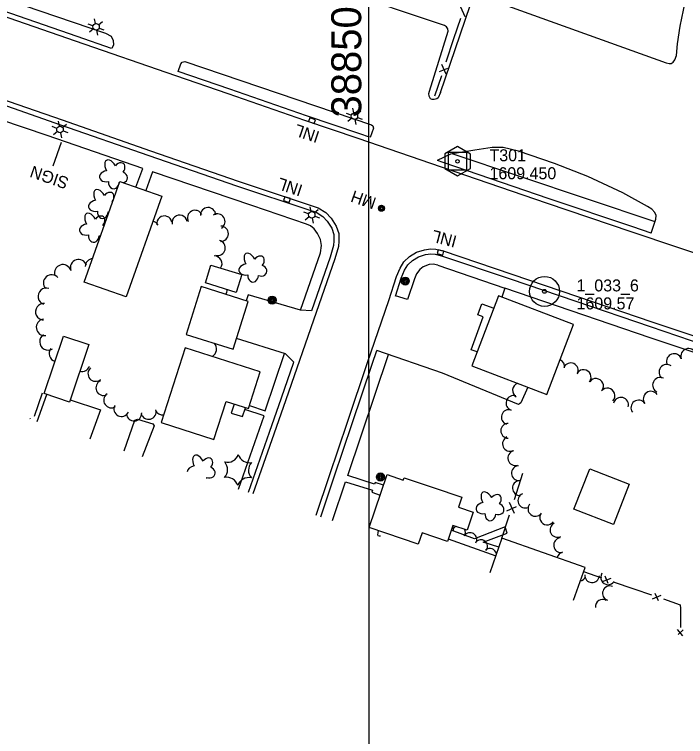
# Model space of a CAD drawing. Extents: x 189384 to 193282, y 256970 to 260388.
# Drawn here: x 191469.2 to 191805.5, y 258599.8 to 258961.6 of the extents above; entities that cross this region are included whole.
import ezdxf

# ---------------------------------------------------------------- set-up
doc = ezdxf.new("R2010")
doc.units = 0
for name, color, linetype in [('E_DRN_Grate', 7, 'Continuous'), ('E_DWY', 7, 'Continuous'), ('E_LAND_Vegetation', 7, 'Continuous'), ('E_MAP_Control', 7, 'Continuous'), ('E_MAP_GridLines', 7, 'Continuous'), ('E_MAP_PassPoints', 7, 'Continuous'), ('E_MISCPROP', 7, 'Continuous'), ('E_MISCPROP_HvyDash', 7, 'Continuous'), ('E_MISCPROP_HvyLine', 7, 'Continuous'), ('E_MISCPROP_Railing', 7, 'Continuous'), ('E_PATH_Sidewalk', 7, 'Continuous'), ('E_RDWY', 7, 'Continuous')]:
    doc.layers.add(name, color=color, linetype=linetype)

# ---------------------------------------------------------------- blocks, each defined once
blk = doc.blocks.new('TP_1')
at = {"layer": 'E_MAP_Control'}
for points in [[(-6.41, 3.76), (-6.41, -3.63), (0.05, -7.35), (6.44, -3.69), (6.44, 3.64), (-0.08, 7.36)], [(-4.5, -4.5), (-4.5, 4.5), (4.5, 4.5), (4.5, -4.5)]]:
    blk.add_lwpolyline(points, close=True, dxfattribs=at)
blk.add_circle((0, 0), 0.871, dxfattribs=at)
blk = doc.blocks.new('PP_1')
at = {"layer": 'E_MAP_PassPoints'}
for radius in [7.5, 0.96]:
    blk.add_circle((0, 0), radius, dxfattribs=at)
blk = doc.blocks.new('LTP')
at = {"layer": 'E_MISCPROP'}
for p, q in [((-0.78, 1.46), (-1.98, 3.76)), ((-1.61, 0.09), (-4.22, 0.17)), ((0.86, 1.37), (2.22, 3.6)), ((1.66, 0), (4.18, -0.06)), ((-0.86, -1.4), (-2.22, -3.59)), ((0.78, -1.44), (2.02, -3.62))]:
    blk.add_line(p, q, dxfattribs=at)
blk.add_circle((0.02, 0.01), 1.64, dxfattribs=at)
blk = doc.blocks.new('POLE')
at = {"layer": 'E_MISCPROP'}
for radius in [2.02, 1.51, 1.01, 0.504]:
    blk.add_circle((0.03, -0.09), radius, dxfattribs=at)
blk = doc.blocks.new('SIGN')
at = {"layer": 'E_MISCPROP'}
blk.add_text('SIGN', height=6, rotation=0, dxfattribs=at).set_placement((0, -3))
blk = doc.blocks.new('MHO')
at = {"layer": 'E_DRN_Grate'}
for centre, radius in [((0.04, -0.06), 1.5), ((0.04, -0.06), 1.22), ((0.04, -0.07), 0.968), ((0.01, -0.08), 0.605)]:
    blk.add_circle(centre, radius, dxfattribs=at)
blk = doc.blocks.new('INLT')
at = {"layer": 'E_MISCPROP_Railing'}
blk.add_lwpolyline([(3, -2), (3, 0), (0, 0), (0, -2), (3, -2)], dxfattribs=at)
blk = doc.blocks.new('INL')
at = {"layer": 'E_MISCPROP_Railing'}
blk.add_text('INL', height=6, rotation=0, dxfattribs=at).set_placement((-5.79, -2.75))
blk = doc.blocks.new('INL_1')
at = {"layer": 'E_MISCPROP_Railing'}
blk.add_text('INL', height=6, rotation=359.9999, dxfattribs=at).set_placement((-5.79, -2.75))
blk = doc.blocks.new('INL_2')
at = {"layer": 'E_MISCPROP_Railing'}
blk.add_text('INL', height=6, rotation=359.9999, dxfattribs=at).set_placement((-5.79, -2.75))
blk = doc.blocks.new('PINEL')
at = {"layer": 'E_LAND_Vegetation'}
for centre, start, end in [((-8.23, 7.26), 275.2112, 0.9761), ((2.17, 10.66), 215.2112, 300.9761), ((10.31, 3.35), 155.2112, 240.9761), ((-10.49, -3.45), 335.2112, 60.9761), ((8.05, -7.36), 95.2112, 180.9761), ((-2.35, -10.75), 35.2112, 120.9761)]:
    blk.add_arc(centre, 5.72, start, end, dxfattribs=at)
blk = doc.blocks.new('TREE')
at = {"layer": 'E_LAND_Vegetation'}
for centre, major_axis, ratio in [((-1.07, 3.38), (0.91, -3.32), 0.782863), ((2.88, 1.66), (-3.52, -1.95), 0.691916), ((-3.74, -0.07), (3.29, -0.08), 0.832022), ((-1.48, -3.66), (1.2, 3.24), 0.716896), ((2.54, -2.64), (-3.34, 3.06), 0.560249)]:
    blk.add_ellipse(centre, major_axis=major_axis, ratio=ratio, start_param=1.570796, end_param=4.712389, dxfattribs=at)

msp = doc.modelspace()

# ---------------------------------------------------------------- linework, layer by layer
at = {"layer": 'E_DWY'}
for points in [[(191682.66, 258922.4), (191681.57, 258919.82), (191680.85, 258919.25), (191679.6, 258918.89), (191678.51, 258918.91), (191677.77, 258919.33), (191677.07, 258920.57), (191676.84, 258921.92), (191677.19, 258923.18), (191686.53, 258953.16), (191686.41, 258954.33), (191685.67, 258955.42), (191684.69, 258956.02), (191631.75, 258973.9), (191560.77, 258998.17), (191543.64, 259004.34), (191515.7, 259014.96)], [(191682.66, 258922.4), (191697.63, 258965.98), (191698.76, 258968.4), (191700.51, 258969.51), (191702.94, 258969.96), (191705.59, 258969.84), (191795.73, 258937.33), (191797.22, 258936.96), (191798.22, 258936.97), (191799.23, 258937.68), (191800.15, 258938.79), (191800.88, 258941.07), (191801.39, 258946.78), (191802.75, 258955.61), (191805.35, 258967.79), (191808.61, 258979.78)], [(191474.06, 258966.02), (191514.83, 258952.16), (191517.69, 258950.67), (191518.63, 258948.55), (191518.85, 258946.38), (191518.04, 258944.49)], [(191551.28, 258933.04), (191552.58, 258936.88), (191553.29, 258937.63), (191554.67, 258937.93), (191648.09, 258906.28), (191648.83, 258905.68), (191649.06, 258904.62), (191647.42, 258899.98)], [(191687.77, 258891.61), (191681.09, 258888.39)], [(191788.32, 258851.94), (191790.65, 258858.94), (191790.82, 258860.82), (191790.02, 258862.35), (191788.56, 258863.96), (191786.42, 258865.34), (191774.08, 258872.21), (191756.54, 258880.45), (191739.78, 258886.8), (191721.84, 258893.13), (191714.16, 258894.97), (191708.54, 258894.84), (191699.89, 258893.63), (191692.76, 258892.35), (191687.77, 258891.61)], [(191681.36, 258835.87), (191679.06, 258836.42), (191677.09, 258836.36), (191673.97, 258835.14), (191672.38, 258833.79), (191670.7, 258831.64), (191669.7, 258829.17), (191666.16, 258818.74), (191660.22, 258820.5)], [(191681.36, 258835.87), (191714.95, 258824.39), (191713.37, 258819.95)], [(191618.11, 258813.14), (191612.52, 258813.41), (191586.27, 258821.14), (191585.3, 258818.16)], [(191701.07, 258792.45), (191698, 258793.58), (191704.14, 258810.01), (191701.45, 258811), (191703.49, 258816.53), (191709.42, 258814.44)], [(191609.14, 258787.36), (191605.05, 258791.47), (191580.55, 258799.15)], [(191683.73, 258781.76), (191650.86, 258793.22)], [(191726.43, 258774.82), (191722.96, 258767.03), (191722.28, 258766.48), (191721.71, 258766.22), (191683.73, 258781.76)], [(191480.62, 258757.62), (191485.46, 258771.16)], [(191497.22, 258768.48), (191512.43, 258763.54), (191506.94, 258748.78)], [(191524.22, 258742.97), (191529.58, 258758.3), (191530.86, 258758.75), (191538.6, 258756.42), (191539.17, 258755.43), (191533.25, 258739.94)]]:
    msp.add_lwpolyline(points, dxfattribs=at)
at = {"layer": 'E_LAND_Vegetation'}
for centre, radius, start, end in [((191559.74, 258859.61), 3.83, 27.8715, 207.8715), ((191566.28, 258860.99), 3.83, 2.1227, 182.1227), ((191544.38, 258856.8), 3.83, 10.2735, 190.2735), ((191552.01, 258857.16), 3.83, 10.6742, 190.6742), ((191570.94, 258857.82), 3.83, 301.7429, 121.7429), ((191537.96, 258854.11), 3.83, 29.4733, 80.6477), ((191572.58, 258851.7), 3.83, 269.0044, 89.0044), ((191571.05, 258844.64), 3.83, 255.7255, 75.7255), ((191501.4, 258834.64), 4.16, 17.978, 197.978), ((191508.88, 258835.12), 4.16, 97.3877, 176.8504), ((191569.42, 258836.73), 3.83, 324.5271, 90.7448), ((191493.48, 258832.07), 4.16, 17.978, 197.978), ((191487.9, 258826.99), 4.16, 41.3306, 221.3306), ((191485.2, 258820.32), 4.16, 71.138, 251.138), ((191573.64, 258823.05), 2.12, 309.3194, 17.5236), ((191483.96, 258812.6), 4.16, 84.7456, 264.7456), ((191484.35, 258804.79), 4.16, 98.2155, 278.2155), ((191486.05, 258797.58), 4.16, 121.8405, 301.8405), ((191490.76, 258791.76), 4.16, 142.9082, 253.7696), ((191566, 258793.99), 4.48, 302.6425, 38.9746), ((191806.95, 258790.35), 3.81, 19.5481, 199.5481), ((191799.76, 258787.8), 3.81, 19.5481, 199.5481), ((191741.09, 258785.06), 3.81, 350.6612, 66.1256), ((191747.92, 258783.16), 3.81, 335.4288, 155.4288), ((191503.2, 258786.54), 3.83, 252.728, 341.5114), ((191509.92, 258781.58), 3.83, 131.1088, 311.1088), ((191754.34, 258779.79), 3.81, 324.1919, 144.1919), ((191796.01, 258782.36), 3.81, 53.6718, 233.6718), ((191792.79, 258775.84), 3.81, 64.7447, 244.7447), ((191513.89, 258774.5), 3.83, 113.7443, 293.7443), ((191722.52, 258773.14), 3.72, 106.3957, 240.2804), ((191760.53, 258775.33), 3.81, 324.1919, 144.1919), ((191766.24, 258770.54), 3.81, 318.7346, 138.7346), ((191788.13, 258768.95), 3.81, 35.8234, 215.8234), ((191517.8, 258768.3), 3.83, 124.108, 304.108), ((191719.26, 258766.87), 3.72, 71.6203, 251.6203), ((191773.11, 258765.9), 3.81, 345.5787, 165.5787), ((191522.9, 258763.97), 3.83, 153.775, 333.775), ((191781.95, 258764.49), 3.81, 35.8234, 215.8234), ((191529.17, 258761.71), 3.83, 183.7674, 3.7674), ((191536.42, 258762.56), 3.83, 194.6491, 14.6491), ((191543.46, 258764.72), 3.83, 203.746, 277.2523), ((191716.92, 258759.81), 3.72, 71.6203, 251.6203), ((191716.64, 258752.95), 3.72, 89.3357, 269.3357), ((191717.51, 258746.47), 3.72, 114.0106, 294.0106), ((191720.21, 258739.29), 3.72, 105.5705, 285.5705), ((191722, 258731.72), 3.72, 93.7356, 273.7356), ((191722.48, 258724.31), 3.72, 93.7356, 273.7356), ((191725.2, 258718.02), 3.72, 113.1747, 293.1747), ((191730.25, 258713.85), 3.72, 141.1629, 321.1629), ((191736.14, 258709.53), 3.72, 145.2348, 325.2348), ((191685.92, 258703.76), 3.32, 346.1121, 28.2953), ((191691.84, 258701.96), 3.32, 112.5783, 149.6827), ((191691.84, 258701.96), 3.32, 329.6827, 29.7957), ((191741.3, 258703.32), 3.72, 116.0333, 296.0333), ((191655.29, 258701.03), 4.1, 153.3738, 190.215), ((191651.58, 258696.17), 4.1, 74.9417, 92.8061), ((191697.55, 258698.6), 3.32, 328.7688, 148.7688), ((191702.97, 258695.03), 3.32, 323.1665, 143.1665), ((191743.13, 258695.63), 3.72, 98.0197, 278.0197), ((191707.51, 258690.67), 3.32, 12.1421, 131.3291), ((191744.74, 258688.53), 3.72, 103.0675, 166.4154), ((191752.18, 258681.44), 3.69, 278.8784, 330.5059), ((191758.64, 258680.62), 3.69, 176.3, 356.3), ((191766.64, 258679.55), 3.69, 146.8525, 326.8525), ((191767.58, 258671.53), 3.69, 69.7676, 249.7676), ((191764, 258664.79), 3.69, 61.0693, 184.5587)]:
    msp.add_arc(centre, radius, start, end, dxfattribs=at)
for centre, major_axis, ratio, start_param, end_param in [((191517.59, 258884.48), (2.16, -3.98), 0.560249, 1.570796, 4.712389), ((191521.73, 258884.14), (-2.19, -2.67), 0.716896, 1.570796, 4.712389), ((191515.87, 258880.53), (3.96, 0.7), 0.691916, 1.570796, 4.712389), ((191522.69, 258880), (-3.08, 1.15), 0.832022, 2.245779, 4.712389), ((191519.04, 258877.61), (0.23, 3.44), 0.782863, 1.570796, 4.275211), ((191519.04, 258877.61), (0.23, 3.44), 0.782863, 4.457873, 4.712389), ((191522.69, 258880), (-3.08, 1.15), 0.832022, 1.570796, 1.616941), ((191512.08, 258869.67), (2.16, -3.98), 0.560249, 1.570796, 4.712389), ((191516.21, 258869.33), (-2.19, -2.67), 0.716896, 1.570796, 4.712389), ((191510.35, 258865.72), (3.96, 0.7), 0.691916, 1.570796, 4.712389), ((191517.17, 258865.19), (-3.08, 1.15), 0.832022, 4.617706, 4.712389), ((191513.52, 258862.8), (0.23, 3.44), 0.782863, 1.570796, 4.712389), ((191507.55, 258857.77), (2.16, -3.98), 0.560249, 1.570796, 4.712389), ((191511.69, 258857.43), (-2.19, -2.67), 0.716896, 1.570796, 4.712389), ((191517.17, 258865.19), (-3.08, 1.15), 0.832022, 1.570796, 1.692635), ((191505.83, 258853.82), (3.96, 0.7), 0.691916, 1.570796, 4.712389), ((191512.65, 258853.29), (-3.08, 1.15), 0.832022, 4.530588, 4.712389), ((191509, 258850.9), (0.23, 3.44), 0.782863, 1.570796, 4.712389), ((191512.65, 258853.29), (-3.08, 1.15), 0.832022, 1.570796, 1.779754), ((191561.55, 258736.62), (2.16, -3.98), 0.560249, 1.570796, 4.712389), ((191565.69, 258736.27), (-2.19, -2.67), 0.716896, 1.570796, 4.712389), ((191559.82, 258732.67), (3.96, 0.7), 0.691916, 1.570796, 3.002871), ((191566.64, 258732.14), (-3.08, 1.15), 0.832022, 1.570796, 4.712389), ((191563, 258729.75), (0.23, 3.44), 0.782863, 4.563977, 4.712389)]:
    msp.add_ellipse(centre, major_axis=major_axis, ratio=ratio, start_param=start_param, end_param=end_param, dxfattribs=at)
at = {"layer": 'E_MAP_GridLines'}
for p, q in [((191647.04, 258512.16), (191646.33, 259512.15)), ((191647.75, 257512.16), (191646.69, 259012.15))]:
    msp.add_line(p, q, dxfattribs=at)
at = {"layer": 'E_MISCPROP'}
msp.add_line((191488.63, 258885.7), (191492.89, 258897.49), dxfattribs=at)
at = {"layer": 'E_MISCPROP_HvyDash'}
msp.add_lwpolyline([(191579.41, 258766.35), (191577.78, 258761.82), (191583.53, 258760.06), (191585.04, 258764.53)], dxfattribs=at)
at = {"layer": 'E_MISCPROP_HvyLine'}
for points in [[(191504.17, 258827.49), (191504.17, 258827.49), (191522.06, 258877.92), (191522.06, 258877.92), (191543.04, 258870.48), (191525.16, 258820.04), (191525.16, 258820.04), (191504.17, 258827.49)], [(191580.37, 258822.22), (191580.37, 258822.22), (191564.9, 258827.03), (191564.9, 258827.03), (191567.69, 258836.02), (191567.69, 258836.02), (191583.16, 258831.21), (191580.37, 258822.22)], [(191578.88, 258793.85), (191586.42, 258817.81), (191586.42, 258817.81), (191586.42, 258817.81), (191562.83, 258825.23), (191555.29, 258801.27), (191555.29, 258801.27), (191555.29, 258801.27)], [(191749.37, 258806.28), (191749.37, 258806.28), (191711.75, 258820.57), (191711.75, 258820.57), (191698.42, 258785.46), (191736.03, 258771.17), (191749.37, 258806.28)], [(191484.17, 258771.6), (191484.17, 258771.6), (191493.86, 258800.43), (191506.53, 258796.17), (191496.84, 258767.34), (191496.84, 258767.34), (191484.17, 258771.6)], [(191569.11, 258748.55), (191569.11, 258748.55), (191575.29, 258767.68), (191575.29, 258767.68), (191586.48, 258764.07), (191586.48, 258764.07), (191592.42, 258782.47), (191592.42, 258782.47), (191554.82, 258794.61), (191542.7, 258757.07), (191542.7, 258757.07), (191542.7, 258757.07)], [(191749.53, 258713.72), (191749.53, 258713.72), (191757.48, 258733.95), (191777.28, 258726.17), (191777.28, 258726.17), (191777.28, 258726.17), (191769.33, 258705.94), (191769.33, 258705.94)], [(191646.93, 258704.46), (191646.93, 258704.46), (191655.97, 258731), (191664.05, 258728.24), (191664.05, 258728.24), (191664.47, 258729.46), (191664.47, 258729.46), (191679.04, 258724.5), (191679.04, 258724.5), (191679.04, 258724.5), (191693.35, 258719.63), (191693.35, 258719.63), (191691.67, 258714.69), (191691.67, 258714.69), (191699.08, 258712.17), (191699.08, 258712.17), (191696.02, 258703.17), (191688.93, 258705.59), (191688.93, 258705.59), (191688.93, 258705.59), (191686.21, 258697.58), (191673.5, 258701.91), (191673.5, 258701.91), (191673.5, 258701.91), (191671.52, 258696.1), (191671.52, 258696.1), (191655.26, 258701.64), (191655.26, 258701.64)]]:
    msp.add_lwpolyline(points, close=True, dxfattribs=at)
msp.add_lwpolyline([(191749.35, 258668.08), (191755.1, 258684.5), (191755.1, 258684.5), (191755.1, 258684.5), (191713.47, 258699.1), (191707.41, 258681.8)], dxfattribs=at)
at = {"layer": 'E_MISCPROP_Railing'}
for p, q in [((191694.99, 258960.31), (191692.93, 258965.24)), ((191685.51, 258931.64), (191683.44, 258936.56)), ((191682.23, 258932.91), (191686.45, 258934.71)), ((191477.24, 258758.75), (191477.08, 258759.15)), ((191715.99, 258712.91), (191720.77, 258714.99)), ((191719.73, 258711.48), (191717.33, 258717.07)), ((191763.86, 258677.4), (191768.21, 258679.18)), ((191765.01, 258680.27), (191766.55, 258676.55)), ((191790.14, 258671.67), (191791.68, 258667.95)), ((191788.99, 258668.8), (191793.34, 258670.58)), ((191801.25, 258653.33), (191804, 258650.21)), ((191804.34, 258653.18), (191801.8, 258650.93))]:
    msp.add_line(p, q, dxfattribs=at)
for points in [[(191689.42, 258949.46), (191692.81, 258959.71)], [(191685.56, 258937.81), (191689.42, 258949.46)], [(191679.93, 258920.79), (191683.32, 258931.03)], [(191479.24, 258760.37), (191483.3, 258772.05)], [(191719.74, 258718.51), (191724.03, 258731.79)], [(191713.47, 258699.1), (191717.25, 258710.78)], [(191754.37, 258682.4), (191763.35, 258679.33)], [(191769.29, 258677.3), (191779.5, 258673.8)], [(191779.5, 258673.8), (191788.48, 258670.73)], [(191794.41, 258668.7), (191802.86, 258665.81), (191802.87, 258663.94)], [(191802.87, 258663.94), (191802.91, 258654.45)]]:
    msp.add_lwpolyline(points, dxfattribs=at)
at = {"layer": 'E_PATH_Sidewalk'}
for points in [[(191530.12, 258875.06), (191533.59, 258884.32), (191485.56, 258900.92), (191450.44, 258912.77), (191446.84, 258901.35), (191457.67, 258888.57), (191458.52, 258887.2), (191458.93, 258885.34), (191458.84, 258883.81), (191458.5, 258882.42), (191445.44, 258844.76), (191441.21, 258846.21)], [(191790.21, 258857.61), (191688.51, 258891.72)], [(191612.64, 258813.41), (191622.51, 258842.1), (191623.02, 258845.88), (191622.64, 258848.88), (191621.03, 258851.76), (191619.41, 258854.07), (191617.65, 258855.61), (191615.55, 258856.51), (191588.13, 258865.84), (191538.38, 258882.7), (191535.07, 258873.3)], [(191876.51, 258769.78), (191787.72, 258799.62), (191714.95, 258824.39)], [(191586.97, 258765.59), (191594.9, 258762.9), (191604.6, 258791.61)], [(191654.19, 258725.78), (191649.98, 258727.11), (191649.67, 258726.28), (191636.35, 258730.51), (191656.73, 258791.18)], [(191594.31, 258760.39), (191584.72, 258763.56)], [(191581.57, 258723.71), (191594.31, 258760.39)], [(191628.52, 258707.94), (191635.18, 258727.37), (191648.56, 258723.3), (191648.27, 258722.18), (191652.48, 258720.76)], [(191711.9, 258694.62), (191704.05, 258697.14), (191716.07, 258701.65), (191715.06, 258704.86), (191699.79, 258698.76), (191688.11, 258703.16)], [(191686.62, 258698.81), (191710.42, 258690.38)]]:
    msp.add_lwpolyline(points, dxfattribs=at)
at = {"layer": 'E_RDWY'}
for points in [[(191517.88, 258944.55), (191500.65, 258950.48), (191454.81, 258966.4), (191410.1, 258981.76), (191374.04, 258994.38), (191324.54, 259011.46)], [(191683.24, 258885.01), (191641.53, 258899.36), (191614.77, 258908.47), (191576.37, 258921.75), (191550.12, 258930.8), (191499.83, 258948.12), (191453.99, 258964.03), (191409.28, 258979.39), (191373.22, 258992.03), (191323.95, 259009.02)], [(191361.24, 258954.06), (191385.46, 258945.84), (191457.32, 258921.18), (191493.21, 258908.68), (191537.38, 258893.31), (191581.32, 258878.07), (191617.48, 258865.99), (191621.41, 258864.71), (191625.31, 258862.26), (191627.96, 258859.54), (191630.51, 258855.55), (191631.7, 258851.73), (191631.82, 258848.04), (191631.62, 258845.37), (191629.73, 258839.16), (191620.45, 258812.27), (191605.2, 258768.42), (191599.22, 258751.24), (191588.76, 258721.3)], [(191381.58, 258944.52), (191384.66, 258943.48), (191456.51, 258918.82), (191492.39, 258906.32), (191536.56, 258890.95), (191580.52, 258875.7), (191616.69, 258863.62), (191620.34, 258862.43), (191623.73, 258860.3), (191625.99, 258857.98), (191628.22, 258854.49), (191629.21, 258851.3), (191629.32, 258848.1), (191629.14, 258845.84), (191627.35, 258839.94), (191618.11, 258813.14)], [(191647.19, 258900.06), (191642.34, 258901.73), (191615.59, 258910.83), (191577.18, 258924.11), (191551.28, 258933.04)], [(191684.05, 258887.37), (191681.12, 258888.38)], [(191824.45, 258837.12), (191778.2, 258852.72), (191736.34, 258866.89), (191683.24, 258885.01)], [(191788.32, 258851.94), (191779, 258855.08), (191737.14, 258869.26), (191684.05, 258887.37)], [(191620.33, 258710.69), (191627.01, 258730.65), (191636.11, 258757.35), (191646.14, 258787.22), (191656.88, 258818.3), (191660.73, 258830.22), (191662.49, 258834.49), (191664.29, 258837.67), (191667.11, 258840.29), (191670.64, 258842.47), (191674.66, 258843.71), (191677.67, 258844.08), (191680.33, 258844.03), (191683.84, 258843.1)], [(191660.21, 258820.49), (191663.07, 258829.36), (191664.74, 258833.4), (191666.27, 258836.1), (191668.63, 258838.29), (191671.68, 258840.17), (191675.18, 258841.26), (191677.8, 258841.58), (191679.98, 258841.54), (191683.2, 258840.68)], [(191684, 258843.05), (191718.4, 258831.4), (191751.39, 258820.27), (191788.5, 258807.62), (191809.06, 258800.63), (191828.87, 258793.85), (191869.09, 258780.19), (191905.01, 258767.95), (191999.53, 258735.73), (192047.75, 258719.3), (192083.01, 258707.19), (192098.65, 258701.93), (192103.66, 258698.73), (192107.92, 258693.73), (192110.64, 258688.87), (192111.86, 258685.6)], [(191683.2, 258840.68), (191717.6, 258829.03), (191750.58, 258817.9), (191787.7, 258805.26), (191808.26, 258798.26), (191828.06, 258791.48), (191868.28, 258777.82), (191874.27, 258775.78)], [(191622.7, 258709.9), (191629.38, 258729.85), (191638.48, 258756.55), (191648.51, 258786.42), (191650.86, 258793.22)], [(191609.08, 258787.19), (191602.83, 258769.24), (191596.86, 258752.06), (191586.39, 258722.09)]]:
    msp.add_lwpolyline(points, dxfattribs=at)

# ---------------------------------------------------------------- block references
at = {"layer": 'E_DRN_Grate', "xscale": 1.0000017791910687, "yscale": 1.000001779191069, "rotation": 160.96088991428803}
msp.add_blockref('MHO', (191653.15, 258864.39), dxfattribs=at)
at = {"layer": 'E_LAND_Vegetation'}
for name, p, xscale, yscale, rotation in [('TREE', (191588.93, 258834.45), 1.0000017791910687, 1.0000017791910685, 160.96089105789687), ('PINEL', (191581.16, 258733.32), 1.0000017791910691, 1.0000017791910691, 160.96089119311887)]:
    msp.add_blockref(name, p, dxfattribs=dict(at, xscale=xscale, yscale=yscale, rotation=rotation))
at = {"layer": 'E_LAND_Vegetation', "rotation": 161.72867818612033}
msp.add_blockref('TREE', (191707.71, 258714.92), dxfattribs=at)
at = {"layer": 'E_MAP_Control', "rotation": 0.00014422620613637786}
msp.add_blockref('TP_1', (191691.24, 258888), dxfattribs=at)
at = {"layer": 'E_MAP_PassPoints', "rotation": 0.000143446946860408}
msp.add_blockref('PP_1', (191734.84, 258822.8), dxfattribs=at)
at = {"layer": 'E_MISCPROP'}
for name, p, xscale, yscale, rotation in [('LTP', (191510.14, 258955.33), 1.000001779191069, 1.0000017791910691, 160.96089246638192), ('LTP', (191639.57, 258910.58), 1.000001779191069, 1.000001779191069, 160.96089015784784), ('LTP', (191492.1, 258903.94), 1.0000017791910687, 1.0000017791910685, 160.96089278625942), ('SIGN', (191496, 258876.71), 1.000001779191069, 1.0000017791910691, 160.9608927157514), ('LTP', (191618.2, 258861.16), 1.0000017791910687, 1.0000017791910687, 160.9608905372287), ('POLE', (191665.05, 258827.88), 1.000001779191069, 1.000001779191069, 160.96088970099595), ('POLE', (191598.35, 258818.32), 1.0000017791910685, 1.0000017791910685, 160.960890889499), ('POLE', (191652.63, 258729.72), 1.0000017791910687, 1.000001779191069, 160.96088991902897)]:
    msp.add_blockref(name, p, dxfattribs=dict(at, xscale=xscale, yscale=yscale, rotation=rotation))
at = {"layer": 'E_MISCPROP_Railing'}
for name, p, rotation in [('INLT', (191619.38, 258906.9), 161.2299594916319), ('INL_1', (191616.26, 258901.97), 161.22995954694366), ('INL_2', (191607.75, 258875.18), 161.53437323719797), ('INLT', (191604.71, 258870.26), -18.46562670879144)]:
    msp.add_blockref(name, p, dxfattribs=dict(at, rotation=rotation))
for name, p, xscale, yscale, rotation in [('INL', (191685.01, 258849.3), 1.0000015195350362, 1.0000015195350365, 165.07686796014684), ('INLT', (191681.53, 258843.71), 1.0000015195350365, 1.0000015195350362, -14.923131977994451)]:
    msp.add_blockref(name, p, dxfattribs=dict(at, xscale=xscale, yscale=yscale, rotation=rotation))

# ---------------------------------------------------------------- texts
at = {"layer": 'E_DRN_Grate'}
msp.add_text('MH', height=6, rotation=160.9608, dxfattribs=at).set_placement((191650.99, 258869.49))
at = {"layer": 'E_MAP_Control'}
for s, p in [('T301', (191707.24, 258888)), ('1609.450', (191707.24, 258879))]:
    msp.add_text(s, height=6, rotation=0, dxfattribs=at).set_placement(p)
at = {"layer": 'E_MAP_GridLines'}
msp.add_text('  388500  ', height=15, rotation=90.0407, dxfattribs=at).set_placement((191643.02, 258898.76))
at = {"layer": 'E_MAP_PassPoints'}
for s, p in [('1_033_6', (191750.84, 258822.8)), ('1609.57', (191750.84, 258813.8))]:
    msp.add_text(s, height=6, rotation=0, dxfattribs=at).set_placement(p)

doc.saveas('drawing.dxf')
